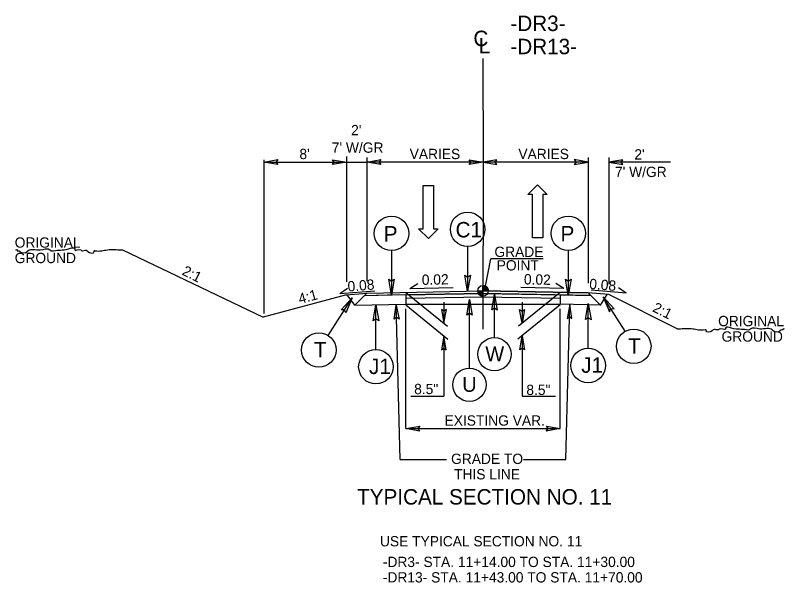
# Model space of a CAD drawing. Extents: x 18938 to 19565, y 6931 to 7973.
# Drawn here: x 19392 to 19466.7, y 7384.5 to 7439.6 of the extents above; entities that cross this region are included whole.
import ezdxf

# ---------------------------------------------------------------- set-up
doc = ezdxf.new("R2010")
doc.units = 0
for name, color, linetype in [('Old_Level_1', 7, 'Continuous'), ('Old_Level_11', 7, 'Continuous'), ('Old_Level_2', 7, 'Continuous'), ('Old_Level_3', 7, 'Continuous'), ('Prop Pavement Schedule Description CELL', 7, 'Continuous'), ('Prop Shade Medium', 7, 'Continuous'), ('Prop Terminator CELL', 7, 'Continuous'), ('Sheet Data Field CELL', 7, 'Continuous'), ('Sheet Plot Border Outside CELL', 7, 'Continuous'), ('Sheet Typical CELL', 7, 'Continuous'), ('Typical Curb CELL', 7, 'Continuous'), ('Typical Detail Wedge1 CELL', 7, 'Continuous'), ('Typical Detail Wedge2 CELL', 7, 'Continuous'), ('Typical Detail Wedge3 CELL', 7, 'Continuous'), ('Typical Hinge Slope Arterial CELL', 7, 'Continuous'), ('Typical ID Circle CELL', 7, 'Continuous'), ('Typical Shoulder Slope Information CELL', 7, 'Continuous'), ('Typical Terminator CELL', 7, 'Continuous'), ('Typical Text General CELL', 7, 'Continuous'), ('Typical Text Grade Point CELL', 7, 'Continuous'), ('Typical Text ID Circle CELL', 7, 'Continuous'), ('Typical Text Label CELL', 7, 'Continuous')]:
    doc.layers.add(name, color=color, linetype=linetype)

msp = doc.modelspace()

# ---------------------------------------------------------------- linework, layer by layer
at = {"layer": 'Old_Level_1'}
for p, q in [((19429.908, 7412.476), (19437.409, 7412.626)), ((19437.409, 7412.626), (19444.908, 7412.476))]:
    msp.add_line(p, q, dxfattribs=at)
at = {"layer": 'Old_Level_3'}
msp.add_line((19424.153, 7425.381), (19426.153, 7425.381), dxfattribs=at)
at = {"layer": 'Prop Pavement Schedule Description CELL'}
for p, q in [((19424.153, 7412.491), (19426.153, 7412.651)), ((19424.975, 7411.473), (19424.22, 7412.496)), ((19424.975, 7411.473), (19426.153, 7412.651)), ((19429.908, 7412.476), (19425.898, 7412.396)), ((19426.153, 7412.651), (19437.409, 7412.876)), ((19447.619, 7412.672), (19437.408, 7412.876)), ((19444.908, 7412.476), (19447.874, 7412.417)), ((19449.619, 7412.512), (19447.619, 7412.672)), ((19448.795, 7411.496), (19447.619, 7412.672)), ((19448.795, 7411.496), (19449.46, 7412.524)), ((19456.308, 7409.167), (19449.619, 7412.512)), ((19424.975, 7411.473), (19429.908, 7411.571)), ((19429.908, 7411.563), (19429.908, 7411.559)), ((19448.795, 7411.496), (19444.908, 7411.574)), ((19444.908, 7411.563), (19444.908, 7411.559))]:
    msp.add_line(p, q, dxfattribs=at)
at = {"layer": 'Prop Shade Medium'}
for p in [(19402.42, 7416.862), (19424.153, 7412.491)]:
    msp.add_line(p, (19416.088, 7410.324), dxfattribs=at)
at = {"layer": 'Sheet Data Field CELL'}
for points in [[(19417.503, 7425.149), (19416.153, 7425.381), (19417.511, 7425.621), (19417.338, 7425.381)], [(19422.803, 7425.614), (19424.153, 7425.381), (19422.796, 7425.141), (19422.968, 7425.381)], [(19427.503, 7425.149), (19426.153, 7425.381), (19427.511, 7425.621), (19427.338, 7425.381)], [(19436.06, 7425.614), (19437.41, 7425.381), (19436.052, 7425.141), (19436.225, 7425.381)], [(19438.76, 7425.614), (19437.41, 7425.381), (19438.767, 7425.141), (19438.595, 7425.381)], [(19446.269, 7425.149), (19447.619, 7425.381), (19446.262, 7425.621), (19446.434, 7425.381)], [(19450.969, 7425.614), (19449.619, 7425.381), (19450.977, 7425.141), (19450.804, 7425.381)], [(19428.802, 7410.134), (19428.999, 7411.49), (19429.274, 7410.139), (19429.03, 7410.305)], [(19446.041, 7410.199), (19445.845, 7411.555), (19445.568, 7410.205), (19445.813, 7410.371)], [(19433.385, 7411.071), (19433.618, 7409.721), (19433.858, 7411.079), (19433.618, 7410.906)], [(19441.432, 7411.071), (19441.199, 7409.721), (19440.959, 7411.079), (19441.199, 7410.906)], [(19433.85, 7407.148), (19433.617, 7408.498), (19433.377, 7407.14), (19433.617, 7407.313)], [(19440.967, 7407.148), (19441.2, 7408.498), (19441.44, 7407.14), (19441.2, 7407.313)], [(19431.258, 7399.262), (19429.908, 7399.494), (19431.266, 7399.734), (19431.093, 7399.494)], [(19443.558, 7399.727), (19444.908, 7399.494), (19443.551, 7399.254), (19443.723, 7399.494)]]:
    msp.add_lwpolyline(points, close=True, dxfattribs=at)
at = {"layer": 'Sheet Typical CELL'}
for p, q in [((19424.153, 7425.915), (19424.153, 7413.98)), ((19426.153, 7425.84), (19426.153, 7413.802)), ((19447.619, 7425.841), (19447.619, 7413.608)), ((19449.619, 7425.819), (19449.619, 7413.534)), ((19416.153, 7425.586), (19416.153, 7410.661)), ((19416.153, 7425.381), (19424.153, 7425.381)), ((19424.153, 7425.586), (19424.153, 7413.74)), ((19447.619, 7425.381), (19426.153, 7425.381)), ((19455.589, 7425.381), (19449.619, 7425.381)), ((19429.908, 7412.726), (19433.964, 7409.441)), ((19444.908, 7412.726), (19440.853, 7409.441)), ((19429.389, 7396.487), (19428.999, 7411.49)), ((19429.908, 7411.502), (19434.013, 7408.177)), ((19433.618, 7411.765), (19433.618, 7409.721)), ((19444.908, 7411.502), (19440.804, 7408.177)), ((19441.199, 7411.765), (19441.199, 7409.721)), ((19445.437, 7396.487), (19445.843, 7411.494)), ((19429.908, 7399.494), (19429.908, 7411.119)), ((19444.908, 7399.494), (19444.908, 7411.119)), ((19433.617, 7408.498), (19433.617, 7402.661)), ((19441.2, 7408.498), (19441.2, 7402.661)), ((19430.393, 7402.661), (19433.617, 7402.661)), ((19441.2, 7402.661), (19444.452, 7402.661)), ((19429.908, 7399.494), (19444.908, 7399.494)), ((19429.389, 7396.487), (19433.877, 7396.487)), ((19441.355, 7396.487), (19445.437, 7396.487))]:
    msp.add_line(p, q, dxfattribs=at)
at = {"layer": 'Typical Curb CELL'}
for points in [[(19392.056, 7416.862), (19392.227, 7416.862), (19392.227, 7416.776), (19392.398, 7416.776), (19392.484, 7416.691), (19393.17, 7416.691), (19393.255, 7416.776), (19394.454, 7416.862), (19395.396, 7416.862), (19395.482, 7416.776), (19395.739, 7416.776), (19397.195, 7416.948), (19397.795, 7416.948), (19397.795, 7416.862), (19398.394, 7416.862), (19398.48, 7416.776), (19398.566, 7416.776), (19398.994, 7416.776), (19399.08, 7416.691), (19399.679, 7416.691), (19399.679, 7416.776), (19399.765, 7416.776), (19400.964, 7416.862), (19402.334, 7416.862), (19402.42, 7416.862)], [(19466.672, 7409.167), (19466.5, 7409.167), (19466.5, 7409.082), (19466.329, 7409.082), (19466.244, 7408.996), (19465.558, 7408.996), (19465.473, 7409.082), (19464.273, 7409.167), (19463.331, 7409.167), (19463.246, 7409.082), (19462.989, 7409.082), (19461.533, 7409.253), (19460.933, 7409.253), (19460.933, 7409.167), (19460.333, 7409.167), (19460.248, 7409.082), (19460.162, 7409.082), (19459.734, 7409.082), (19459.648, 7408.996), (19459.049, 7408.996), (19459.049, 7409.082), (19458.963, 7409.082), (19457.764, 7409.167), (19456.393, 7409.167), (19456.308, 7409.167)]]:
    msp.add_spline(points, degree=3, dxfattribs=at)
at = {"layer": 'Typical Detail Wedge1 CELL'}
for p, q in [((19437.409, 7412.876), (19437.409, 7413.388)), ((19436.896, 7412.876), (19437.409, 7412.876)), ((19437.408, 7412.364), (19437.409, 7412.876)), ((19437.409, 7412.876), (19437.408, 7412.364)), ((19437.921, 7412.876), (19437.409, 7412.876))]:
    msp.add_line(p, q, dxfattribs=at)
for points in [[(19437.414, 7413.388), (19437.414, 7413.388), (19437.414, 7412.876)], [(19437.424, 7413.387), (19437.424, 7412.876)], [(19437.434, 7413.387), (19437.434, 7412.876)], [(19437.445, 7413.387), (19437.444, 7412.876)], [(19437.455, 7413.385), (19437.455, 7412.876)], [(19437.465, 7413.385), (19437.465, 7412.876)], [(19437.475, 7413.384), (19437.475, 7412.876)], [(19437.485, 7413.382), (19437.485, 7412.876)], [(19437.496, 7413.38), (19437.495, 7412.876)], [(19437.506, 7413.378), (19437.506, 7412.876)], [(19437.516, 7413.376), (19437.516, 7412.876)], [(19437.526, 7413.374), (19437.526, 7412.876)], [(19437.537, 7413.372), (19437.536, 7412.876)], [(19437.547, 7413.369), (19437.547, 7412.876)], [(19437.557, 7413.366), (19437.557, 7412.876)], [(19437.567, 7413.363), (19437.567, 7412.876)], [(19437.578, 7413.359), (19437.577, 7412.876)], [(19437.588, 7413.355), (19437.587, 7412.876)], [(19437.598, 7413.352), (19437.598, 7412.876)], [(19437.608, 7413.347), (19437.608, 7412.876)], [(19437.619, 7413.343), (19437.619, 7412.876)], [(19437.629, 7413.338), (19437.629, 7412.876)], [(19437.639, 7413.333), (19437.639, 7412.876)], [(19437.649, 7413.328), (19437.649, 7412.876)], [(19437.66, 7413.322), (19437.659, 7412.876)], [(19437.67, 7413.316), (19437.67, 7412.876)], [(19437.68, 7413.31), (19437.68, 7412.876)], [(19437.69, 7413.303), (19437.69, 7412.876)], [(19437.7, 7413.297), (19437.7, 7412.876)], [(19437.711, 7413.289), (19437.711, 7412.876)], [(19437.721, 7413.281), (19437.721, 7412.876)], [(19437.731, 7413.273), (19437.731, 7412.876)], [(19437.741, 7413.265), (19437.741, 7412.876)], [(19437.752, 7413.256), (19437.751, 7412.876)], [(19437.762, 7413.246), (19437.762, 7412.876)], [(19437.772, 7413.236), (19437.772, 7412.876)], [(19437.782, 7413.226), (19437.782, 7412.876)], [(19437.792, 7413.214), (19437.792, 7412.876)], [(19437.803, 7413.202), (19437.803, 7412.876)], [(19437.813, 7413.189), (19437.813, 7412.876)], [(19437.823, 7413.176), (19437.823, 7412.876)], [(19437.834, 7413.161), (19437.834, 7412.876)], [(19437.844, 7413.145), (19437.844, 7412.876)], [(19437.854, 7413.128), (19437.854, 7412.876)], [(19437.864, 7413.11), (19437.864, 7412.876)], [(19437.875, 7413.088), (19437.874, 7412.876)], [(19437.885, 7413.064), (19437.885, 7412.876)], [(19437.895, 7413.036), (19437.895, 7412.876)], [(19437.905, 7413), (19437.905, 7412.876)], [(19437.915, 7412.948), (19437.915, 7412.876)], [(19436.899, 7412.876), (19436.899, 7412.82)], [(19436.91, 7412.876), (19436.91, 7412.76)], [(19436.92, 7412.876), (19436.92, 7412.722)], [(19436.93, 7412.876), (19436.93, 7412.693)], [(19436.941, 7412.876), (19436.941, 7412.668)], [(19436.951, 7412.876), (19436.951, 7412.646)], [(19436.961, 7412.876), (19436.961, 7412.627)], [(19436.971, 7412.876), (19436.971, 7412.61)], [(19436.982, 7412.876), (19436.982, 7412.594)], [(19436.992, 7412.876), (19436.992, 7412.578)], [(19437.002, 7412.876), (19437.002, 7412.565)], [(19437.012, 7412.876), (19437.012, 7412.552)], [(19437.022, 7412.876), (19437.022, 7412.54)], [(19437.033, 7412.876), (19437.033, 7412.528)], [(19437.043, 7412.876), (19437.043, 7412.517)], [(19437.053, 7412.876), (19437.053, 7412.507)], [(19437.063, 7412.876), (19437.063, 7412.498)], [(19437.074, 7412.876), (19437.073, 7412.489)], [(19437.084, 7412.876), (19437.084, 7412.48)], [(19437.094, 7412.876), (19437.094, 7412.472)], [(19437.104, 7412.876), (19437.104, 7412.464)], [(19437.115, 7412.876), (19437.115, 7412.457)], [(19437.125, 7412.876), (19437.125, 7412.449)], [(19437.135, 7412.876), (19437.135, 7412.443)], [(19437.145, 7412.876), (19437.145, 7412.436)], [(19437.156, 7412.876), (19437.156, 7412.43)], [(19437.166, 7412.876), (19437.166, 7412.425)], [(19437.176, 7412.876), (19437.176, 7412.42)], [(19437.186, 7412.876), (19437.186, 7412.414)], [(19437.197, 7412.876), (19437.196, 7412.41)], [(19437.207, 7412.876), (19437.207, 7412.405)], [(19437.217, 7412.876), (19437.217, 7412.401)], [(19437.227, 7412.876), (19437.227, 7412.397)], [(19437.238, 7412.876), (19437.238, 7412.393)], [(19437.248, 7412.876), (19437.248, 7412.389)], [(19437.258, 7412.876), (19437.258, 7412.386)], [(19437.268, 7412.876), (19437.268, 7412.383)], [(19437.278, 7412.876), (19437.278, 7412.38)], [(19437.289, 7412.876), (19437.288, 7412.378)], [(19437.299, 7412.876), (19437.299, 7412.376)], [(19437.309, 7412.876), (19437.309, 7412.373)], [(19437.319, 7412.876), (19437.319, 7412.372)], [(19437.33, 7412.876), (19437.33, 7412.37)], [(19437.34, 7412.876), (19437.34, 7412.368)], [(19437.35, 7412.876), (19437.35, 7412.367)], [(19437.361, 7412.876), (19437.36, 7412.366)], [(19437.371, 7412.876), (19437.371, 7412.365)], [(19437.381, 7412.876), (19437.381, 7412.365)], [(19437.391, 7412.876), (19437.391, 7412.364)], [(19437.401, 7412.876), (19437.401, 7412.364), (19437.401, 7412.364)]]:
    msp.add_lwpolyline(points, dxfattribs=at)
msp.add_circle((19437.409, 7412.876), 0.512, dxfattribs=at)
for start, end in [(359.99048, 89.99048), (179.99048, 269.99048)]:
    msp.add_arc((19437.409, 7412.876), 0.512, start, end, dxfattribs=at)
at = {"layer": 'Typical Detail Wedge3 CELL'}
for p, q in [((19431.616, 7418.894), (19431.616, 7423.094)), ((19431.616, 7423.094), (19432.606, 7423.094)), ((19432.606, 7423.094), (19432.606, 7418.894)), ((19441.761, 7422.223), (19442.691, 7423.168)), ((19442.691, 7423.168), (19443.651, 7422.223)), ((19442.211, 7422.223), (19441.761, 7422.223)), ((19442.211, 7418.023), (19442.211, 7422.223)), ((19443.651, 7422.223), (19443.201, 7422.223)), ((19443.201, 7422.223), (19443.201, 7418.023)), ((19432.126, 7417.949), (19431.166, 7418.894)), ((19431.166, 7418.894), (19431.616, 7418.894)), ((19433.056, 7418.894), (19432.126, 7417.949)), ((19432.606, 7418.894), (19433.056, 7418.894)), ((19443.201, 7418.023), (19442.211, 7418.023))]:
    msp.add_line(p, q, dxfattribs=at)
at = {"layer": 'Typical Hinge Slope Arterial CELL'}
for p, q in [((19425.898, 7412.396), (19426.153, 7412.651)), ((19428.153, 7412.441), (19425.898, 7412.396)), ((19426.153, 7412.651), (19437.409, 7412.876)), ((19437.409, 7412.626), (19428.153, 7412.441)), ((19428.153, 7412.441), (19428.153, 7412.441)), ((19437.409, 7412.876), (19447.619, 7412.672)), ((19447.874, 7412.417), (19437.409, 7412.626)), ((19447.619, 7412.672), (19447.874, 7412.417))]:
    msp.add_line(p, q, dxfattribs=at)
at = {"layer": 'Typical ID Circle CELL'}
for p, q in [((19429.908, 7412.476), (19429.908, 7411.563)), ((19429.908, 7412.158), (19437.408, 7412.308)), ((19437.408, 7412.308), (19444.908, 7412.158)), ((19444.908, 7412.476), (19444.908, 7411.563)), ((19444.908, 7411.563), (19429.908, 7411.563))]:
    msp.add_line(p, q, dxfattribs=at)
at = {"layer": 'Typical Terminator CELL'}
for p, q in [((19428.537, 7416.78), (19428.537, 7412.448)), ((19435.921, 7417.177), (19435.921, 7412.846)), ((19445.685, 7416.791), (19445.685, 7412.46)), ((19422.383, 7408.544), (19424.709, 7412.197)), ((19438.516, 7408.336), (19438.516, 7412.52)), ((19451.201, 7408.944), (19449.063, 7412.301)), ((19427.023, 7407.183), (19427.023, 7411.514)), ((19436.089, 7405.374), (19436.089, 7412.027)), ((19447.613, 7407.302), (19447.613, 7411.633))]:
    msp.add_line(p, q, dxfattribs=at)
for centre, radius in [((19435.921, 7418.853), 1.676), ((19428.537, 7418.455), 1.676), ((19445.685, 7418.467), 1.676), ((19421.483, 7407.13), 1.676), ((19452.034, 7407.49), 1.676), ((19438.516, 7406.718), 1.619), ((19427.023, 7405.507), 1.676), ((19447.613, 7405.626), 1.676), ((19436.089, 7403.755), 1.619)]:
    msp.add_circle(centre, radius, dxfattribs=at)
at = {"layer": 'Typical Text General CELL'}
for points in [[(19428.804, 7414), (19428.537, 7412.448), (19428.261, 7414.009), (19428.537, 7413.811)], [(19436.189, 7414.398), (19435.921, 7412.846), (19435.645, 7414.407), (19435.921, 7414.208)], [(19445.952, 7414.012), (19445.685, 7412.46), (19445.409, 7414.021), (19445.685, 7413.822)], [(19423.65, 7411.032), (19424.709, 7412.197), (19424.104, 7410.733), (19423.978, 7411.048)], [(19438.258, 7411.021), (19438.516, 7412.52), (19438.783, 7411.013), (19438.516, 7411.204)], [(19450.122, 7411.136), (19449.063, 7412.301), (19449.668, 7410.837), (19449.795, 7411.152)], [(19426.756, 7409.962), (19427.023, 7411.514), (19427.299, 7409.953), (19427.023, 7410.152)], [(19435.831, 7410.528), (19436.089, 7412.027), (19436.356, 7410.52), (19436.089, 7410.712)], [(19447.346, 7410.081), (19447.613, 7411.633), (19447.889, 7410.073), (19447.613, 7410.271)]]:
    msp.add_lwpolyline(points, close=True, dxfattribs=at)
at = {"layer": 'Typical Text Grade Point CELL'}
for p, q in [((19423.524, 7412.614), (19424.278, 7413.133)), ((19430.313, 7413.116), (19431.096, 7413.589)), ((19430.313, 7413.116), (19434.502, 7413.2)), ((19445.257, 7413.116), (19441.068, 7413.2)), ((19445.257, 7413.116), (19444.474, 7413.589)), ((19451.294, 7412.656), (19450.54, 7413.175)), ((19423.524, 7412.614), (19426.91, 7412.885)), ((19451.294, 7412.656), (19447.908, 7412.927))]:
    msp.add_line(p, q, dxfattribs=at)
at = {"layer": 'Typical Text ID Circle CELL'}
for p, q in [((19437.408, 7435.456), (19437.41, 7425.381)), ((19437.41, 7425.381), (19437.408, 7409.14)), ((19437.659, 7413.329), (19438.154, 7415.997)), ((19443.231, 7415.996), (19438.154, 7415.997))]:
    msp.add_line(p, q, dxfattribs=at)

# ---------------------------------------------------------------- texts
at = {"layer": 'Old_Level_11'}
for s, height, p in [('TYPICAL SECTION NO. 11', 1.5, (19425.197, 7392.121)), ('USE TYPICAL SECTION NO. 11', 1, (19427.414, 7388.057))]:
    msp.add_text(s, height=height, dxfattribs=at).set_placement(p)
at = {"layer": 'Old_Level_2'}
for s, p in [('ORIGINAL', (19391.979, 7417.069)), ('GROUND', (19391.979, 7415.569))]:
    msp.add_text(s, height=1, rotation=360, dxfattribs=at).set_placement(p)
for s, p in [('ORIGINAL', (19460.222, 7409.442)), ('GROUND', (19460.558, 7407.942))]:
    msp.add_text(s, height=1, dxfattribs=at).set_placement(p)
at = {"layer": 'Prop Terminator CELL'}
for s, height, p in [('P', 1.5, (19427.784, 7417.667)), ('C1', 1.5, (19434.748, 7418.065)), ('P', 1.5, (19444.932, 7417.679)), ('T', 1.5, (19451.49, 7406.77)), ('W', 1.449, (19437.637, 7406.03)), ('J1', 1.5, (19426.351, 7404.795)), ('J1', 1.5, (19446.941, 7404.915)), ('U', 1.449, (19435.394, 7403.068))]:
    msp.add_text(s, height=height, dxfattribs=at).set_placement(p)
msp.add_text('T', height=1.5, rotation=360, dxfattribs=at).set_placement((19421.014, 7406.41))
at = {"layer": 'Sheet Plot Border Outside CELL'}
for s, p in [('GRADE', (19438.519, 7416.165)), ('POINT', (19438.738, 7414.854))]:
    msp.add_text(s, height=1, rotation=0.00004, dxfattribs=at).set_placement(p)
at = {"layer": 'Typical Detail Wedge2 CELL'}
for s, p in [("2'", (19424.614, 7427.989)), ("7' W/GR", (19422.738, 7426.289)), ("8'", (19419.599, 7425.671)), ('VARIES', (19430.295, 7425.671)), ('VARIES', (19440.84, 7425.671)), ("2'", (19452.094, 7425.631)), ("7' W/GR", (19450.218, 7423.931)), ('8.5"', (19430.732, 7402.843)), ('8.5"', (19441.618, 7402.763)), ('EXISTING VAR.', (19433.68, 7399.784)), ('GRADE TO', (19434.313, 7396.062)), ('THIS LINE', (19434.604, 7394.562)), ('-DR3- STA. 11+14.00 TO STA. 11+30.00', (19427.694, 7386.05)), ('-DR13- STA. 11+43.00 TO STA. 11+70.00', (19427.694, 7384.55))]:
    msp.add_text(s, height=1, dxfattribs=at).set_placement(p)
at = {"layer": 'Typical Shoulder Slope Information CELL'}
for s, rotation, p in [('2:1', 333.43491, (19408.129, 7414.484)), ('4:1', 15.1346, (19419.644, 7411.591)), ('2:1', 333.43491, (19453.777, 7410.918))]:
    msp.add_text(s, height=1, rotation=rotation, dxfattribs=at).set_placement(p)
at = {"layer": 'Typical Text Grade Point CELL'}
for s, rotation, p in [('0.02', 1.14574, (19431.48, 7413.451)), ('0.02', 358.85426, (19441.372, 7413.505)), ('0.08', 4.5738, (19424.312, 7412.803)), ('0.08', 355.4262, (19447.69, 7413.069))]:
    msp.add_text(s, height=1, rotation=rotation, dxfattribs=at).set_placement(p)
at = {"layer": 'Typical Text Label CELL'}
for s, p in [('-DR3- ', (19440.068, 7438.11)), ('C', (19436.48, 7436.646)), ('L', (19436.996, 7435.94)), ('-DR13-', (19440.068, 7435.86))]:
    msp.add_text(s, height=1.5, dxfattribs=at).set_placement(p)

doc.saveas('drawing.dxf')
